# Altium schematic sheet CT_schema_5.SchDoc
size 252 x 159 mm
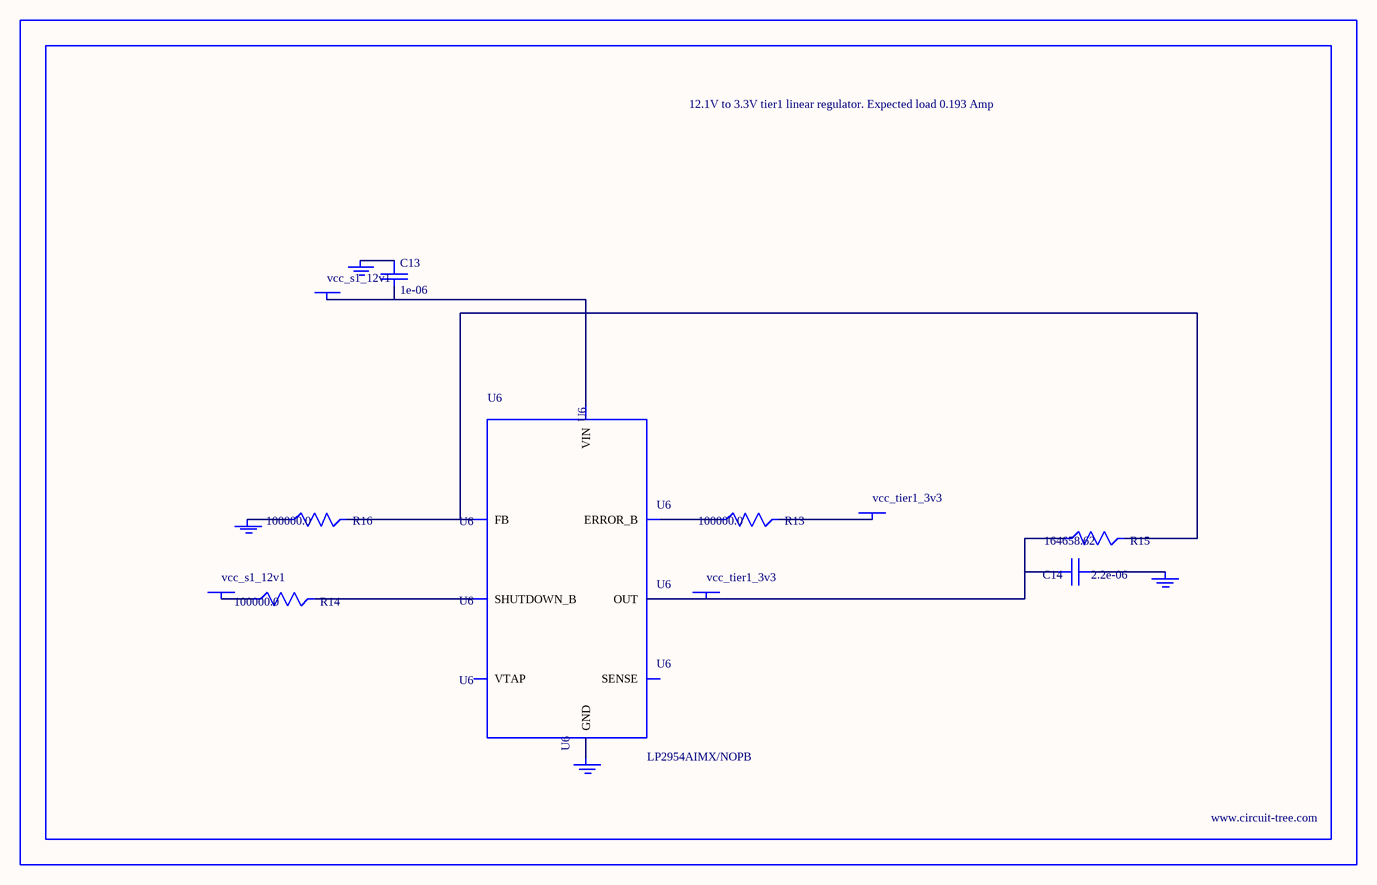
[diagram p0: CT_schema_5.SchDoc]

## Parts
BORDER4  (no value)
C13  1e-06  [EXV-9B]
C14  2.2e-06  [EXV-9B]
GND_INSTANCE_4_0  (no value)
GND_INSTANCE_4_1  (no value)
GND_INSTANCE_4_2  (no value)
GND_INSTANCE_4_3  (no value)
POWER_INSTANCE_4_0  vcc_s1_12v1
POWER_INSTANCE_4_1  vcc_tier1_3v3
POWER_INSTANCE_4_2  vcc_s1_12v1
POWER_INSTANCE_4_3  vcc_tier1_3v3
R13  100000.0  [R0603]
R14  100000.0  [R0603]
R15  164658.62  [R0603]
R16  100000.0  [R0603]
U6  LP2954AIMX/NOPB  [LP2954]

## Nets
NetC13_1: C13.1 GND_INSTANCE_4_2.0(GND)
NetC13_2: C13.2 POWER_INSTANCE_4_2.0(PWR) U6.8(VIN)
NetC14_1: C14.1 GND_INSTANCE_4_0.0(GND)
NetC14_2: C14.2 POWER_INSTANCE_4_3.0(PWR) R15.1 U6.1(OUT)
NetGND_INSTANCE_4_1_0: GND_INSTANCE_4_1.0(GND) R16.1
NetGND_INSTANCE_4_3_0: GND_INSTANCE_4_3.0(GND) U6.4(GND)
NetPOWER_INSTANCE_4_0_0: POWER_INSTANCE_4_0.0(PWR) R14.1
NetPOWER_INSTANCE_4_1_0: POWER_INSTANCE_4_1.0(PWR) R13.2
NetR13_1: R13.1 U6.5(ERROR_B)
NetR14_2: R14.2 U6.3(SHUTDOWN_B)
NetR15_2: R15.2 R16.2 U6.7(FB)

Not connected (* = marked no-connect by the designer): U6 2(SENSE) 6(VTAP)

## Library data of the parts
BORDER4 = BORDER_PAGE4
C13 = EDK105M050A9BAA
C14 = EDK225M050A9BAA
GND_INSTANCE_4_0-GND_INSTANCE_4_3 = GND
POWER_INSTANCE_4_0-POWER_INSTANCE_4_3 = PWR
R13 R14 R16 = RC0603JR-07100KL
R15 = R15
